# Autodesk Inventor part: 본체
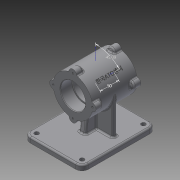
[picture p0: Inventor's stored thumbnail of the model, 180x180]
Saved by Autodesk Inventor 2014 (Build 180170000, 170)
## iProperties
Created: 2015-12
Part Number: 본체
Material: 일반
Document SubType Name: Modeling
Designer: L6
Density: 1 g/cm^3
Appearance: 기본값
Author: L6
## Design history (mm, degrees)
sketch "스케치1"
  geometry: L1 (-42.5, 37)-(42.5, 37); L2 (42.5, 37)-(42.5, 0); L3 (42.5, 0)-(-42.5, 0); L4 (-42.5, 0)-(-42.5, 37); L5 (-42.5, 23.5)-(-20.5, 23.5); L6 (-20.5, 23.5)-(-20.5, 21); L7 (-20.5, 21)-(20.5, 21); L8 (20.5, 21)-(20.5, 23.5); L9 (20.5, 23.5)-(42.5, 23.5); 2 further points
  constraints: 18 end point, 4 parallel, 4 perpendicular, 2 collinear, 2 point on line, 1 coincident, 1 horizontal, 1 midpoint
  dimensions: "d0" = 85 distance of L1.start L1.end; "d1" = 37 distance of L3.end L1.start; "d2" = 23.5 distance between parallel lines of L3 L5; "d3" = 21 distance between parallel lines of L3 L7; "d4" = 22 distance of L5.start L5.end
revolve "회전1" sketch "스케치1" stored, may be unused: angle "d5" = 90 deg
sketch "스케치3"
  geometry: L1 (-42.5, 37)-(42.5, 37) reference; L2 (-42.5, 37)-(-27.5, 37); L3 (-42.5, 37)-(-42.5, 44); L4 (-42.5, 44)-(-30.048, 44); L5 (-27.5, 37)-(-30.048, 44); 1 further point
  constraints: 8 end point, 2 perpendicular, 1 point on line
  dimensions: "d6" = 15 distance of L1.start L2.end; "d7" = 7 distance of L1.start L3.end; "d8" = 110 deg angle of L1 L5
revolve "회전2" sketch "스케치3" stored, may be unused: angle "d9" = 90 deg
hole "구멍1" diameter "d15" = 3.242; stored, may be unused: countersink angle "d19" = 90 deg, drill point angle "d21" = 118 deg; dims "d13" = 10, "d14" = 10, "d16" = 9, "d17" = 4, "d18" = 2, "d20" = 10
hole "구멍2" diameter "d24" = 3.242; stored, may be unused: countersink angle "d28" = 90 deg, drill point angle "d30" = 118 deg; dims "d22" = 10, "d23" = 10, "d25" = 9, "d26" = 4, "d27" = 2, "d29" = 10
hole "구멍3" diameter "d33" = 3.242; stored, may be unused: countersink angle "d37" = 90 deg, drill point angle "d39" = 118 deg; dims "d31" = 10, "d32" = 10, "d34" = 9, "d35" = 4, "d36" = 2, "d38" = 10
hole "구멍4" diameter "d42" = 3.242; stored, may be unused: countersink angle "d46" = 90 deg, drill point angle "d48" = 118 deg; dims "d40" = 10, "d41" = 10, "d43" = 9, "d44" = 4, "d45" = 2, "d47" = 10
node "작업 평면1"
sketch "스케치5"
  geometry: L1 (-55, 60)-(55, 60); L2 (55, 60)-(55, -80); L3 (55, -80)-(-55, -80); L4 (-55, -80)-(-55, 60); 1 further point
  constraints: 8 end point, 2 parallel, 1 horizontal, 1 perpendicular
  dimensions: "d50" = 110 distance of L1.start L1.end; "d51" = 140 distance of L3.end L1.start; "d52" = 80 distance from line of point (0, 0) L3; "d53" = 55 distance from line of point (0, 0) L4
extrude "돌출1" join sketch "스케치5" distance "d54" = 10; taper "d55" = 0 deg
fillet "모깎기1" dims "d56" = 12
hole "구멍5" diameter "d59" = 8; stored, may be unused: countersink angle "d63" = 90 deg, drill point angle "d65" = 118 deg; dims "d57" = 10, "d58" = 10, "d60" = 9, "d61" = 4, "d62" = 2, "d64" = 10
hole "구멍6" diameter "d68" = 8; stored, may be unused: countersink angle "d72" = 90 deg, drill point angle "d74" = 118 deg; dims "d66" = 10, "d67" = 10, "d69" = 9, "d70" = 4, "d71" = 2, "d73" = 10
hole "구멍7" diameter "d77" = 8; stored, may be unused: countersink angle "d81" = 90 deg, drill point angle "d83" = 118 deg; dims "d75" = 10, "d76" = 10, "d78" = 9, "d79" = 4, "d80" = 2, "d82" = 10
hole "구멍8" diameter "d86" = 8; stored, may be unused: countersink angle "d90" = 90 deg, drill point angle "d92" = 118 deg; dims "d84" = 10, "d85" = 10, "d87" = 9, "d88" = 4, "d89" = 2, "d91" = 10
sketch "스케치6"
  geometry: L1 (43, -70)-(55, -70) reference; L2 (39, -70)-(47, -70) reference; L3 (-43, -70)-(43, -70) reference; L4 (-47, -70)-(-39, -70) reference; L5 (37, 0)-(37, -70); L6 (-37, 0)-(-37, -70); A1 r 37 centre (0, 0) between (6.969, -36.338) and (36.338, -6.969) reference; A2 r 7 centre (37, 0) between (36.338, -6.969) and (36.338, 6.969) reference; A3 r 37 centre (0, 0) between (-36.338, -6.969) and (-6.969, -36.338) reference; A4 r 7 centre (-37, 0) between (-36.338, 6.969) and (-36.338, -6.969) reference; A5 r 37 centre (0, 0) between (-37, 0) and (37, 0); 1 further point
  constraints: 4 end point, 2 perpendicular, 2 point on circle, 2 point on line, 1 centre point, 1 coincident, 2 other
extrude "돌출2" join sketch "스케치6" stored distance "d93" = 8; taper "d94" = 0 deg
sketch "스케치7"
  geometry: L1 (-27.5, -37)-(27.5, -37) reference; L2 (48, -70)-(-68, -70) reference; L3 (-25, -70)-(-20.948, -37); 1 further point
  constraints: 2 end point, 2 point on line
  dimensions: "d95" = 25 horizontal distance of L3.start point (0, 0); "d96" = 97 deg angle of L2 L3
feature "리브1" sketch "스케치7" dims "d97" = 1, "d98" = 12, "d99" = 0, "d100" = 0, "d101" = 1, "d102" = 1
sketch "스케치8"
  geometry: L1 (0, 0)-(0, 59.369); L2 (0, 0)-(-35.355, 35.355)
  constraints: 4 end point, 1 vertical
  dimensions: "d103" = 50 distance of L1.start L2.end; "d104" = 45 deg angle of L2 L1
node "작업 평면2"
sketch "스케치9"
  geometry: 2 further points
  constraints: 1 coincident, 1 other
feature "엠보싱1" sketch "스케치9" dims "d0" = 85, "d1" = 37, "d2" = 23.5, "d3" = 21, "d4" = 22, "d105" = 0.5, "d106" = 0
chamfer "모따기1" distance "d107" = 1; stored, may be unused: second distance "d108" = 2, angle "d109" = 45 deg
fillet "모깎기2" dims "d110" = 0.3
fillet "모깎기3" dims "d111" = 3
fillet "모깎기5" dims "d113" = 3
node "솔리드1"
pattern_circular "원형 패턴1" dims angle "d11" = 360 deg
mirror "대칭1"
mirror "대칭2"
pattern_circular "원형 패턴2" dims angle "d117" = 360 deg
mirror "대칭3"
